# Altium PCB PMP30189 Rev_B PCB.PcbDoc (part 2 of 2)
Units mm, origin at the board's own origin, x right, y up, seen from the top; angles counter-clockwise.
Board outline 62.23 x 71.12 mm, 4 copper layers (Top Layer, Signal Layer 1, Signal Layer 2, Bottom Layer), stack 2.099 mm thick; 88 components, 42 nets, 247 pads, 90 vias.
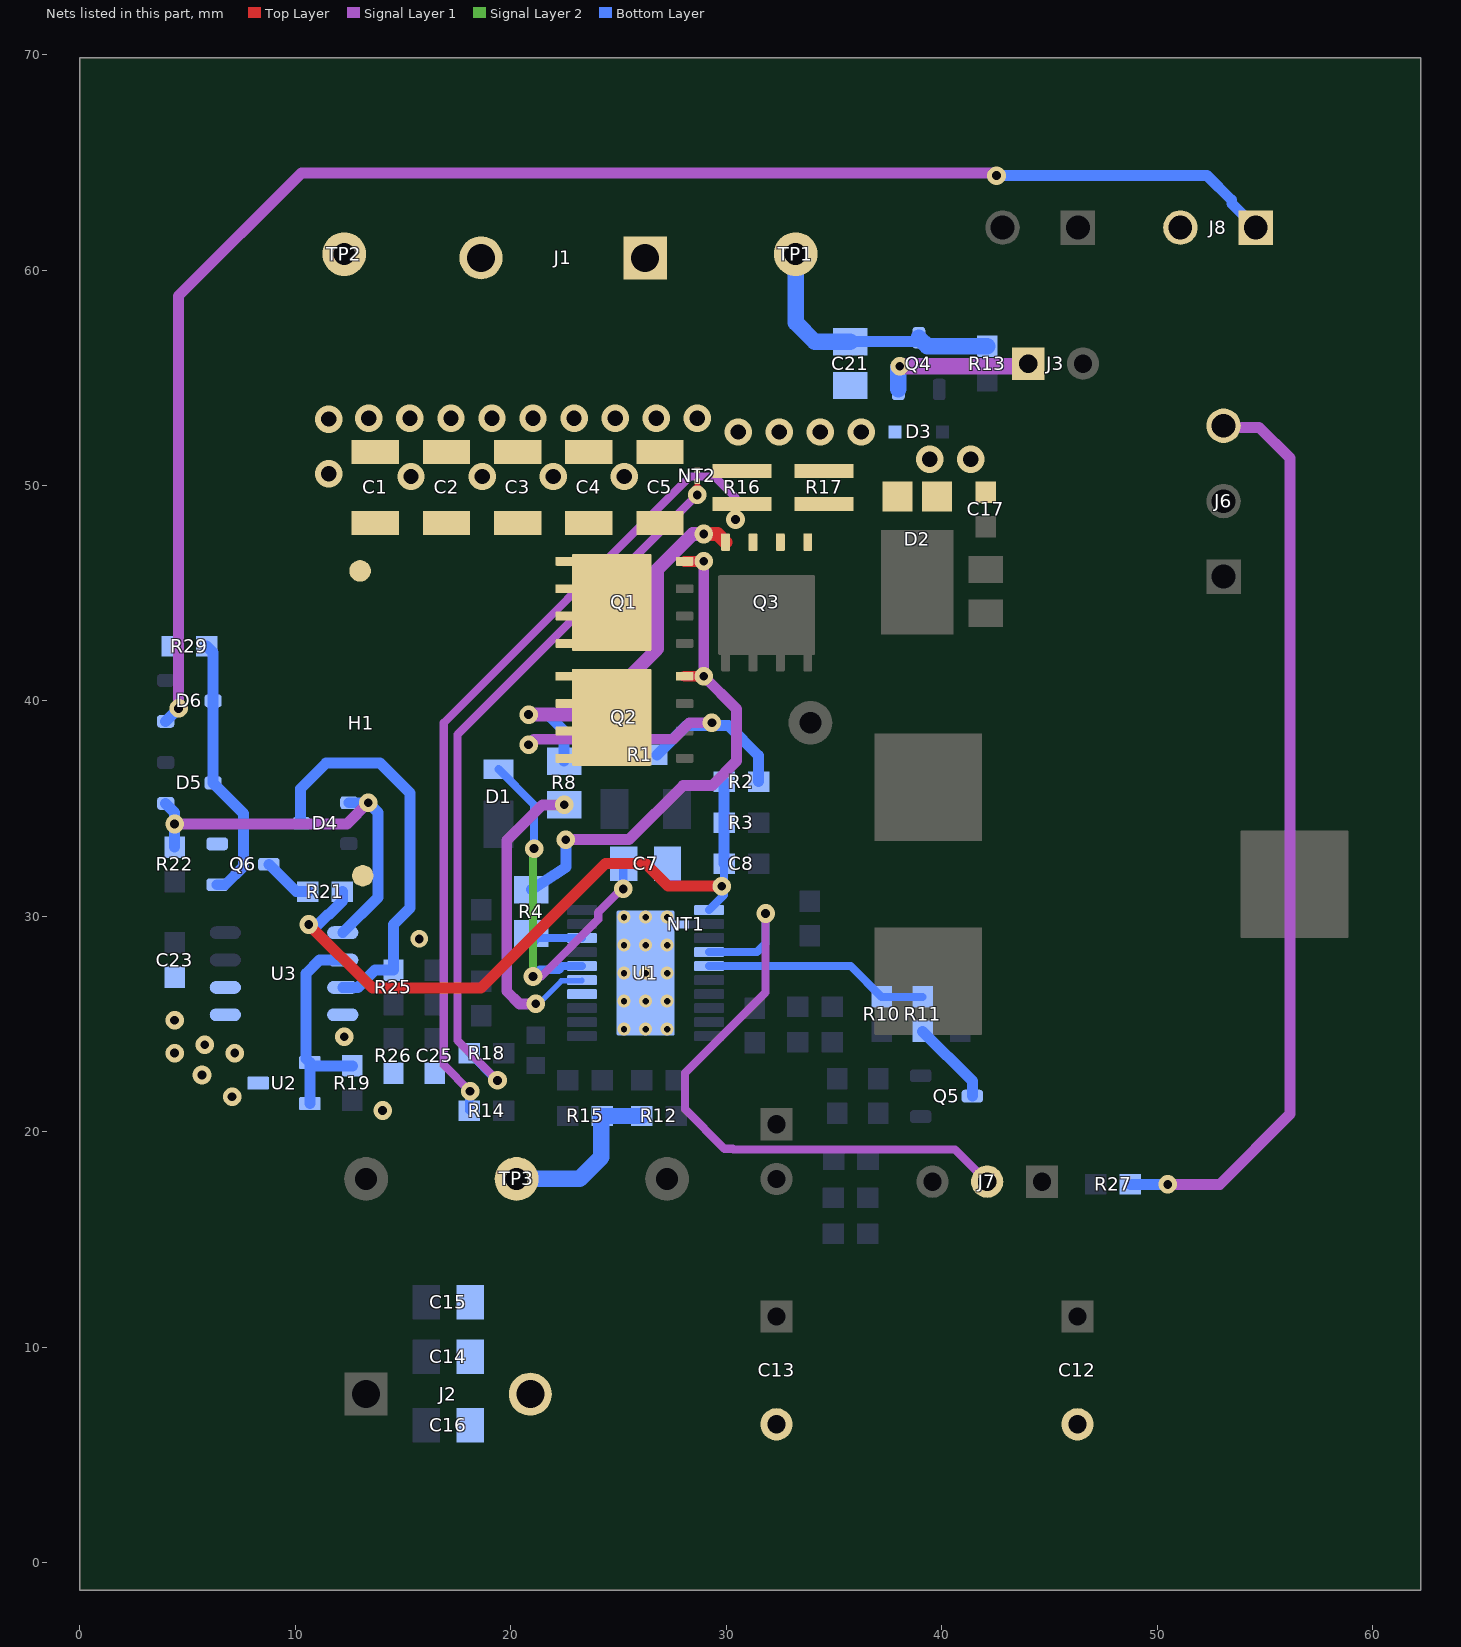
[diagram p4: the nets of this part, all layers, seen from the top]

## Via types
v1: diameter 0.864, hole 0.406, Top Layer to Bottom Layer, 51 vias
v2: diameter 1.27, hole 0.711, Top Layer to Bottom Layer, 21 vias
v3: diameter 0.6, hole 0.3, Top Layer to Bottom Layer, 9 vias
v4: diameter 0.6, hole 0.3, Top Layer to Bottom Layer, tented both sides, 6 vias
v5: diameter 0.813, hole 0.406, Top Layer to Bottom Layer, 2 vias
v6: diameter 0.864, hole 0.406, Top Layer to Bottom Layer, tented bottom, 1 vias

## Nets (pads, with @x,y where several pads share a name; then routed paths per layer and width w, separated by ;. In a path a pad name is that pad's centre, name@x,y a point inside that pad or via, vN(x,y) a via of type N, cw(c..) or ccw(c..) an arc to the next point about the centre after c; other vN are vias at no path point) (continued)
NetD4_1: D4.1 D5.1 R22.2 U3.1 | length 19.4
  Signal Layer 1 w0.508: v1(4.395,34.29) 12.395,34.29 v1(13.381,35.275)
  Bottom Layer w0.508: D5.1@3.98,35.245 4.395,34.83 v1(4.395,34.29) R22.2@4.395,33.22 ; U3.1@12.2,29.245 13.83,30.875 13.83,34.825 v1(13.381,35.275) D4.1@12.48,35.275
NetD4_3: D4.3 R25.2 U3.3 | length 19
  Bottom Layer w0.508: D4.3@10.28,34.325 10.237,34.368 10.237,35.925 11.431,37.119 13.92,37.119 15.317,35.722 15.317,30.388 14.555,29.626 R25.2@14.555,27.505 13.704,27.505 12.904,26.705 U3.3@12.2,26.705
NetD5_3: D5.3 D6.3 Q6.1 R29.2 | length 12.5
  Bottom Layer w0.508: R29.2@5.88,42.545 6.18,42.245 D6.3@6.18,40.005 D5.3@6.18,36.195 7.595,34.78 7.595,32.32 6.746,31.47 Q6.1@6.37,31.47
NetJ3_1: J3.1 Q4.2 | length 7.1
  Signal Layer 1 w0.762: v1(38.05,55.534) 43.892,55.534 J3.1@44.019,55.661
  Bottom Layer w0.762: Q4.2@37.989,54.461 37.989,55.473 v1(38.05,55.534)
NetJ6_3: J6.3 R27.1 | length 42.9
  Signal Layer 1 w0.508: v1(50.496,17.561) 52.909,17.561 56.171,20.823 56.171,51.271 54.737,52.705 53.157,52.705 J6.3@53.086,52.776
  Bottom Layer w0.508: R27.1@48.756,17.561 v1(50.496,17.561)
NetJ7_2: J7.2 U1.4 | length 30.2
  Signal Layer 1 w0.381: v1(31.827,30.134) 31.827,26.471 28.084,22.728 28.084,21.05 29.922,19.212 30.303,19.212 30.336,19.179 40.623,19.179 J7.2@42.114,17.688
  Bottom Layer w0.381: U1.4@29.205,28.345 31.435,28.345 31.827,28.737 v1(31.827,30.134)
NetNT2_1: NT2.1 R18.2 | length 34.8
  Top Layer w0.381: v1(28.652,49.565) v1@28.652,49.911
  Signal Layer 1 w0.381: v1@19.454,22.46 v1(19.381,22.387) 17.526,24.243 17.526,38.439 v1(28.652,49.565)
  Bottom Layer w0.381: R18.2@18.073,23.657 19.343,22.387 v1(19.381,22.387)
NetQ1_4: Q1.4 Q2.4 R4.2 | length 24.3
  Top Layer w0.508: Q2.4@28.068,41.148 v1(28.956,41.148) ; Q1.4@28.068,46.482 v1(28.956,46.482)
  Signal Layer 1 w0.508: v6(22.556,33.563) 25.486,33.563 27.991,36.068 29.337,36.068 30.48,37.211 30.48,39.624 v1(28.956,41.148) v1(28.956,46.482)
  Bottom Layer w0.508: R4.2@20.955,31.242 22.556,32.284 v6(22.556,33.563)
NetQ3_1: Q3.1 Q3.2 Q3.3 R14.2 R16.2 R17.2 | length 39.1
  Top Layer w0.381: v1(30.43,48.422) 30.43,48.917 R16.2@30.684,49.171
  Signal Layer 1 w0.381: v1(18.111,21.879) 16.891,23.1 16.891,38.989 28.321,50.419 29.464,50.419 30.43,49.453 v1(30.43,48.422)
  Bottom Layer w0.381: R14.2@18.073,20.99 18.073,21.841 v1(18.111,21.879)
NetQ3_4: Q3.4 R8.2 | length 18.3
  Top Layer w0.635: v1(28.956,47.752) 29.592,47.752 Q3.4@29.972,47.372
  Signal Layer 1 w0.635: v1(20.828,39.37) 23.749,39.37 26.797,42.418 26.797,46.101 28.448,47.752 v1(28.956,47.752)
  Bottom Layer w0.508: v1(20.828,39.37) 21.717,39.37 22.479,38.608 R8.2@22.479,37.211
NetQ5_3: Q5.3 R11.1 | length 4
  Bottom Layer w0.508: R11.1@39.116,24.665 41.425,22.356 Q5.3@41.425,21.655
NetQ6_3: Q6.3 R21.1 | length 2.3
  Bottom Layer w0.508: Q6.3@8.77,32.42 10.04,31.15 R21.1@10.58,31.15
NetR4_1: R4.1 U1.18 | length 2.4
  Bottom Layer w0.381: R4.1@21.032,28.776 21.251,28.995 U1.18@23.305,28.995
NetR8_1: R8.1 U1.15 | length 14.6
  Signal Layer 1 w0.508: v1(21.159,25.943) 20.397,25.943 19.812,26.529 19.812,33.528 21.463,35.179 v1(22.479,35.179)
  Bottom Layer w0.254: v1(21.159,25.943) 21.286,25.943 22.347,27.004 23.305,27.004 U1.15@23.305,27.045
NetR10_2: R10.2 R11.2 U1.5 | length 10.5
  Bottom Layer w0.381: U1.5@29.205,27.695 35.781,27.695 R10.2@37.211,26.265 R11.2@39.116,26.265
NetR12_1: R12.1 R15.2 TP3.1 | length 8.1
  Bottom Layer w0.762: TP3.1@20.27,17.815 23.191,17.815 24.207,18.831 24.207,20.698 R15.2@24.245,20.736 R12.1@26.074,20.736
NetR19_2: R19.2 U2.1 U2.2 U3.2 | length 10.1
  Bottom Layer w0.508: U2.2@10.675,21.31 U2.1@10.675,23.21 ; U3.2@12.2,27.975 11.126,27.975 10.491,27.34 10.491,23.394 U2.1@10.675,23.21 ; R19.2@12.65,23.06 10.826,23.06 U2.1@10.675,23.21
ON-OFF: D6.1 J8.1 | length 73.5
  Signal Layer 1 w0.508: v1(4.58,39.655) 4.58,58.809 10.287,64.516 42.418,64.516 v1(42.545,64.389)
  Bottom Layer w0.508: D6.1@3.98,39.055 v1(4.58,39.655) ; v1(42.545,64.389) 52.324,64.389 53.467,63.246 53.467,63.091 J8.1@54.582,61.976
OVV_24V: C8.1 R2.1 R3.2 R21.2 U1.1 | length 31.9
  Top Layer w0.508: v1(10.618,29.626) 13.573,26.672 18.619,26.672 24.397,32.45 26.255,32.45 27.301,31.404 v1(29.795,31.404)
  Bottom Layer w0.381: U1.1@29.205,30.295 29.9,30.99 C8.1@29.9,32.45
  Bottom Layer w0.508: v1(10.618,29.626) 11.043,29.626 11.507,30.09 11.557,30.09 12.18,30.713 R21.2@12.18,31.15 ; C8.1@29.9,32.45 R3.2@29.9,34.355 29.9,35.341 R2.1@29.9,36.26
SGND: C1.2 C2.2 C3.2 C4.2 C5.2 C7.2 C12.2 C13.2 C14.2 C15.2 C16.2 C17.2 C21.2 C23.2 C25.1 D2.1 D2.2 D3.2 J1.2 J2.2 J8.2 NT1.2 NT2.2 Q6.2 R16.1 R17.1 R26.1 R29.1 TP2.1 U1.14 U1.21@26.255,27.37 U2.3 U3.4 U3.5 U3.6
  other v1: 14.047,20.99 7.062,21.625 5.665,22.641 4.395,23.657 7.189,23.657 5.792,24.038 12.269,24.419 4.395,25.181
  other v2: 15.367,50.419 18.669,50.419 21.971,50.419 25.273,50.419 11.557,50.546 39.447,51.216 41.352,51.216 30.557,52.486 32.462,52.486 34.367,52.486 36.272,52.486 11.557,53.086 13.412,53.121 15.317,53.121 17.222,53.121 19.127,53.121 21.032,53.121 22.937,53.121 24.842,53.121 26.747,53.121 28.652,53.121
  other v3: 25.255,26.07 26.255,26.07 27.255,26.07 25.255,27.37 26.255,27.37 27.255,27.37 25.255,28.67 26.255,28.67 27.255,28.67
  other v4: 25.255,24.77 26.255,24.77 27.255,24.77 25.255,29.97 26.255,29.97 27.255,29.97
  other v5: 15.748,28.956
VCC-1: C7.1 D1.2 U1.16 | length 19.7
  Signal Layer 1 w0.381: v1@21.413,27.213 24.056,29.855 24.056,30.173 25.033,31.15 25.223,31.15 v1(25.223,31.277)
  Signal Layer 2 w0.381: v1(21.032,27.213) 21.032,33.097 v1(21.082,33.147)
  Bottom Layer w0.381: D1.2@19.431,36.835 21.082,35.184 v1(21.082,33.147) ; v1(21.032,27.213) 21.34,27.521 22.229,27.521 22.403,27.695 U1.16@23.305,27.695 ; v1(25.223,31.277) 25.223,32.434 C7.1@25.239,32.45
VIN: C1.1 C2.1 C3.1 C4.1 C5.1 C21.1 H1.1 H1.2 J1.1 Q1.5 Q1.6 Q1.7 Q1.8 Q1.9@24.683,44.577 Q2.5 Q2.6 Q2.7 Q2.8 Q2.9@24.683,39.243 Q4.3 R1.1 R2.2 R13.2 TP1.1 | length 28.7
  Signal Layer 1 w0.508: v1(20.828,37.973) 21.08,38.225 27.535,38.225 28.299,38.989 v1(29.337,38.989)
  Bottom Layer w0.508: R1.1@26.785,37.5 28.147,38.862 30.099,38.862 31.5,37.461 R2.2@31.5,36.26 ; C21.1@35.764,56.677 38.755,56.677 Q4.3@38.939,56.861
  Bottom Layer w0.762: TP1.1@33.224,60.741 33.224,57.566 34.114,56.677 C21.1@35.764,56.677 ; Q4.3@38.939,56.861 39.339,56.461 R13.2@42.114,56.461
pads on no net: D4.2 D5.2 D6.2 L1.3 Q1.9@23.873,43.127 Q1.9@23.873,44.577 Q1.9@23.873,46.027 Q1.9@25.653,43.127 Q1.9@25.653,44.577 Q1.9@25.653,46.027 Q2.9@23.873,37.793 Q2.9@23.873,39.243 Q2.9@23.873,40.693 Q2.9@25.653,37.793 Q2.9@25.653,39.243 Q2.9@25.653,40.693 Q3.9@30.427,43.177 Q3.9@30.427,44.957 Q3.9@31.877,43.177 Q3.9@31.877,44.957 Q3.9@33.327,43.177 Q3.9@33.327,44.957 U1.7 U1.10 U1.21@26.255,27.37 U3.7

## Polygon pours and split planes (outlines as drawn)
GND-1 on Bottom Layer "Bottom Layer-No Net" (solid, pour order 2): 37.034,36.357 36.399,36.992 27.255,36.992 26.493,36.23 26.493,35.976 26.493,32.039 28.36,30.173 28.455,30.173 28.455,24.32 28.398,24.263 28.398,23.82 28.236,23.657 24.969,23.657 23.318,23.657 22.937,23.276 22.937,21.662 22.937,20.011 26.657,16.291 28.88,14.069 39.003,14.069 40.209,15.275 40.251,21.793 40.251,23.105 40.209,23.146 40.209,26.705 37.796,29.118 37.796,29.626 37.796,35.595
SGND on Bottom Layer "S-GND Bottom" (solid, pour order 16): 1.279,67.31 59.514,67.31 59.513,0.797 59.64,0.67 1.267,0.67
24V on Bottom Layer "+24V Bottom" (solid, pour order 0): 9.602,14.005 17.095,14.005 17.095,3.845 9.602,3.845
GND-1 on Signal Layer 2 "Bottom Layer-No Net" (solid, pour order 4): 37.034,36.357 36.399,36.992 27.255,36.992 26.493,36.23 26.493,35.976 26.493,32.039 28.36,30.173 28.455,30.173 28.455,24.32 28.398,24.263 28.398,23.82 28.235,23.657 23.318,23.657 22.937,23.276 22.937,21.662 22.937,20.011 26.657,16.291 34.748,16.291 40.251,21.793 40.251,23.105 40.209,23.146 40.209,26.705 37.796,29.118 37.796,29.626 37.796,35.595
SGND on Signal Layer 2 "S-GND Mid-2" (solid, pour order 14): 1.281,67.31 59.514,67.31 59.513,0.797 59.64,0.67 1.269,0.67
SGND on Top Layer "TOP_LAYER_SGND_P020" (solid, remove dead copper, pour order 20): 24.638,23.876 28.194,23.876 29.718,25.4 29.718,29.972 29.21,30.48 23.368,30.48 21.849,28.961 21.849,25.764 23.045,24.568 23.94,24.568
NetC9_2 on Top Layer "Switch Node" (solid, pour order 6): 27.051,45.974 27.051,46.353 37.237,46.353 37.251,46.353 38.53,47.776 43.13,47.776 43.13,40.307 43.13,33.147 35.687,33.147 35.687,36.83 27.051,36.83
NetQ3_1 on Top Layer "Top Layer-No Net" (solid, pour order 8): 29.287,49.946 36.829,49.946 36.829,45.974 29.287,45.974
SGND on Top Layer "Signal Layer 1-No Net" (solid, pour order 10): 9.602,54.899 9.729,54.899 39.066,54.899 42.876,51.089 42.876,48.93 42.495,48.549 42.235,48.549 37.796,48.549 37.415,48.93 37.415,50.073 37.161,50.327 29.668,50.327 27.636,50.327 27.065,49.756 9.602,49.756
VIN on Top Layer "Vin" (solid, pour order 12): 1.397,67.091 59.64,67.091 59.64,56.55 58.497,55.407 9.348,55.407 8.713,54.772 8.713,49.132 26.797,49.132 26.797,33.613 22.126,28.942 1.397,28.942
24V on Top Layer "+24V" (solid, pour order 18): 1.27,19.735 33.292,19.735 34.42,20.863 34.42,25.615 36.703,27.898 36.703,31.369 38.646,31.369 49.911,31.369 57.75,23.53 59.514,21.767 59.513,22.888 59.513,0.73 59.466,0.683 2.618,0.683 1.27,2.03

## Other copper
Top Layer:
  rectangle net SGND: 28.144,50.327 31.192,51.089

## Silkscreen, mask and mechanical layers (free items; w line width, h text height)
Top Overlay:
  lines w0.254: 57.15,66.04 59.309,66.04
  text "-" at 17.78,68.961 h2.03 r180
  text "Vin" at 25.273,68.707 h2.03 r180
  text "+" at 27.051,68.453 h2.03 r270
  text "7V" at 46.863,67.691 h1.02 r180
  text "GND" at 51.562,67.564 h1.02 r180
  text "Fsw" at 42.799,67.437 h1.02 r180
  text "ON/OFF" at 59.055,67.437 h1.02 r180
  text "Vin-Trk" at 60.325,51.435 h1.02 r90
  text "GND" at 58.547,47.752 h1.02 r90
  text "Vout-Trk" at 60.452,41.148 h1.02 r90
  text "'.PRJ_Number'.PCB_Rev-" at 59.309,4.318 h2.75 r90
  text "+" at 10.16,1.905 h2.03 r270
  text "-" at 22.86,1.905 h2.03 r180
  text "Vout" at 13.97,0 h1.78
Top Solder:
  rectangle: 24.892,24.384 27.686,30.353
M1 Board Outline:
  the board outline again, w0.254
M2 Board Dimensions:
  rectangle: 0,-6.985 3.175,-3.81
  rectangle: 3.175,-10.16 12.7,-6.985
  lines w0.178: 0,-6.985 25.4,-6.985 ; 3.175,-10.16 3.175,-3.81 ; 6.35,-10.16 6.35,-3.81 ; 12.7,-10.16 12.7,-3.81 ; 19.05,-10.16 19.05,-3.81 ; 0,-10.16 25.4,-10.16 25.4,-3.81 0,-3.81 0,-10.16
M5 Assembly Top:
  lines w0.254: -7.417,-23.626 160.223,-23.626 ; -7.417,-18.462 160.274,-18.462 ; -7.417,-13.297 -7.417,-28.791 94.31,-28.791 160.274,-28.791 160.274,-13.297 -7.404,-13.297 -7.404,-28.791 32.614,-28.791 ; 55.194,-28.791 55.194,-13.297 ; 87.376,-18.462 87.376,-13.297 ; 108.712,-18.462 108.712,-13.297 ; 124.511,-28.956 124.511,-23.804
  text "COMPONENTS MARKED 'DNP' SHOULD NOT BE POPULATED." at 29.299,-8.09 h1.52
  text "ASSEMBLY VARIANT:" at 29.286,-11.024 h1.52
  text ".VariantName" at 55.601,-11.024 h1.52
  text "BOARD #:" at 57.099,-16.654 h1.52
  text ".PRJ_Number" at 70.955,-16.654 h1.52
  text "REV:" at 92.405,-16.654 h1.52
  text ".PCB_Rev" at 99.809,-16.654 h1.52
  text "SVN REV:" at 113.69,-16.654 h1.52
  text ".VersionControl_RevNumber" at 126.543,-16.654 h1.52
  text "TID #:" at 57.099,-21.819 h1.52
  text ".TID" at 70.955,-21.819 h1.52
  text "PLOT NAME =" at -5.804,-27.034 h1.52
  text ".plot_File_Name" at 14.656,-27.034 h1.52
  text "GENERATED    :" at 57.15,-27.034 h1.52
  text ".Print_Date" at 79.235,-27.034 h1.52
  text ".Print_Time" at 97.752,-27.034 h1.52
  text "TEXAS INSTRUMENTS" at 129.87,-27.034 h1.52
M6 Assembly Bottom:
  lines w0.254: -7.429,-18.474 160.261,-18.474 ; -7.379,-23.639 160.261,-23.639 ; 28.334,-28.969 28.334,-23.817 ; 44.133,-18.474 44.133,-13.31 ; 65.468,-18.474 65.468,-13.31 ; 97.65,-28.804 97.65,-13.31 ; 120.231,-28.804 160.249,-28.804 160.249,-13.31 -7.429,-13.31 -7.429,-28.804 58.534,-28.804 160.261,-28.804 160.261,-13.31
  text "COMPONENTS MARKED 'DNP' SHOULD NOT BE POPULATED." at 154.991,-8.077 h1.52
  text ".VariantName" at 128.473,-11.024 h1.52
  text "ASSEMBLY VARIANT:" at 154.864,-11.024 h1.52
  text ".PCB_Rev" at 53.035,-16.667 h1.52
  text "REV:" at 60.439,-16.667 h1.52
  text ".PRJ_Number" at 81.89,-16.667 h1.52
  text "BOARD #:" at 95.745,-16.667 h1.52
  text "PCB VIEWED FROM BOTTOM SIDE" at 158.648,-16.667 h1.52
  text ".TID" at 81.89,-21.831 h1.52
  text "TID #:" at 95.745,-21.831 h1.52
  text "TEXAS INSTRUMENTS" at 22.974,-27.047 h1.52
  text ".Print_Time" at 55.093,-27.047 h1.52
  text ".Print_Date" at 73.609,-27.047 h1.52
  text "GENERATED    :" at 95.694,-27.047 h1.52
  text ".plot_File_Name" at 138.189,-27.047 h1.52
  text "PLOT NAME =" at 158.648,-27.047 h1.52
M9 Title Sheet:
  drawing of 57 lines, arcs and shapes, not listed
  text "1" at 18.792,204.127 h1.78
  text "2" at 82.182,204.127 h1.78
  text "3" at 145.411,204.127 h1.78
  text "4" at 209.08,204.127 h1.78
  text "5" at 272.555,204.127 h1.78
  text "6" at 336.182,204.127 h1.78
  text "A" at -10.579,175.095 h1.78
  text "A" at 365.341,175.095 h1.78
  text "B" at -10.579,114.643 h1.78
  text "B" at 365.341,114.643 h1.78
  text "C" at -10.579,54.318 h1.78
  text "C" at 365.341,54.318 h1.78
  text "PROJECT TITLE:" at 288.125,7.048 h1.14
  text ".PRJ_Title" at 289.395,3.662 h1.78
  text "DESIGNED FOR:" at 288.125,-0.597 h1.14
  text ".PRJ_Customer" at 289.395,-4.153 h1.78
  text "D" at -10.579,-5.88 h1.78
  text "D" at 365.341,-5.88 h1.78
  text "FILE NAME:" at 288.125,-8.217 h1.14
  text ".PCB_File_Name_No_Path" at 289.395,-11.265 h1.78
  text "Texas Instruments (TI) and/or its licensors do not warrant the accuracy or completeness of this specification" at 161.9,-15.376 h1.14
  text "ENGINEER:" at 288.125,-15.583 h1.14
  text "LAYOUT BY:" at 326.352,-15.583 h1.14
  text "or any information contained therein. TI and/or its licensors do not warrant that this design will meet" at 160.757,-18.237 h1.14
  text ".PRJ_Engineer" at 289.395,-19.52 h1.78
  text ".PCB_Layout" at 327.635,-19.52 h1.78
  text "the specifications, will be suitable for your application or fit for any particular purpose, or will operate in" at 160.757,-21.099 h1.14
  text "ALTIUM DESIGNER VERSION:" at 326.352,-23.457 h1.14
  text "an implementation. TI and/or its licensors do not warrant that the design is production worthy. You should" at 160.757,-23.961 h1.14
  text "completely validate and test your design implementation to confirm the system functionality for your application." at 161.9,-26.822 h1.14
  text ".print_Scale" at 289.395,-26.843 h1.78
  text ".Application_BuildNumber" at 327.635,-26.843 h1.78
  text "1" at 18.792,-32.093 h1.78
  text "2" at 82.182,-32.093 h1.78
  text "3" at 145.411,-32.093 h1.78
  text "4" at 209.08,-32.093 h1.78
  text "5" at 272.555,-32.093 h1.78
  text "6" at 336.182,-32.093 h1.78
M10 Fab Notes:
  drawing of 173 lines, arcs and shapes, not listed
  text "DESIGN INFORMATION" at 314.402,157.505 h1.52
  text "MIN. TRACK WIDTH:" at 298.03,152.933 h1.52
  text "8" at 325.874,152.933 h1.52
  text "MIL" at 329.805,152.933 h1.52
  text "MIN. CLEARANCE:" at 298.03,149.581 h1.52
  text "0.2" at 324.35,149.581 h1.52
  text "mm" at 329.805,149.581 h1.52
  text "MIN. VIA PAD SIZE:" at 298.03,146.228 h1.52
  text "24" at 325.113,146.228 h1.52
  text "MIL" at 329.805,146.228 h1.52
  text "0.05mm (2MIL)" at 315.683,142.628 h1.52
  text "MINIMUM ANNULAR RING" at 289.667,142.52 h1.52
  text "EXTERNAL" at 333.666,142.52 h1.52
  text "PER" at 294.747,139.522 h1.52
  text "IPC-D-275 CLASS 2 LEVEL C" at 300.335,139.522 h1.52
  text "MIL, HOLES" at 338.136,136.67 h1.52
  text "+/-" at 328.168,136.652 h1.52
  text "+/-" at 349.86,136.652 h1.52
  text "REGISTRATION TOLERANCES:" at 289.667,136.525 h1.52
  text "METAL" at 320.142,136.525 h1.52
  text "5" at 334.777,136.525 h1.52
  text "3" at 355.935,136.525 h1.52
  text "MIL" at 358.888,136.525 h1.52
  text "+/-" at 349.86,133.655 h1.52
  text "HOLE SIZE TOLERANCE (UNLESS OTHERWISE SPECIFIED):" at 289.667,133.528 h1.52
  text "3" at 355.935,133.528 h1.52
  text "MIL" at 358.888,133.528 h1.52
  text "MATERIAL:" at 287.768,128.208 h1.52
  text "FR-4 High Tg" at 312.824,124.643 h1.52
  text "FR-408" at 298.462,124.425 h1.52
  text "OTHER" at 336.257,124.425 h1.52
  text "X" at 308.889,124.333 h1.52
  text "62 MIL (1.6mm) +/-10%" at 306.592,120.292 h1.52
  text "THICKNESS:" at 289.667,120.184 h1.52
  text "X" at 303.337,120.184 h1.52
  text "OTHER" at 339.229,120.184 h1.52
  text "TOLERANCE:" at 289.667,116.17 h1.52
  text "X" at 310.986,116.17 h1.52
  text "ANSI IPC-6012 TYPE 3 CLASS 2" at 315.734,116.17 h1.52
  text "OTHER +/-" at 315.734,112.208 h1.52
  text "BOW & TWIST:" at 289.667,108.22 h1.52
  text "X" at 310.986,108.22 h1.52
  text "ANSI IPC-6012 TYPE 3 CLASS 2" at 315.734,108.22 h1.52
  text "OTHER +/-" at 315.734,104.194 h1.52
  text "DRILLING:" at 287.768,100.676 h1.52
  text "REFERENCE:" at 289.667,97.705 h1.52
  text "X" at 306.132,97.705 h1.52
  text "AS SHOWN" at 310.882,97.705 h1.52
  text "X" at 329.018,97.705 h1.52
  text "NC_DRILL FILES" at 332.498,97.705 h1.52
  text "PTH COPPER THICKNESS:" at 289.667,93.691 h1.52
  text "X" at 318.375,93.691 h1.52
  text "20-30 um" at 321.855,93.691 h1.52
  text "OTHER" at 340.067,93.691 h1.52
  text "BOARD FINISH:" at 287.768,89.653 h1.52
  text "SILKSCREEN:" at 291.711,86.656 h1.52
  text "X" at 315.81,86.656 h1.52
  text "TOP" at 319.01,86.656 h1.52
  text "X" at 328.764,86.656 h1.52
  text "BOTTOM" at 331.99,86.656 h1.52
  text "SILKSCREEN COLOR:" at 291.711,82.414 h1.52
  text "X" at 315.783,82.414 h1.52
  text "WHITE" at 319.01,82.414 h1.52
  text "OTHER" at 331.99,82.414 h1.52
  text "X" at 319.111,78.37 h1.52
  text "GREEN" at 322.338,78.37 h1.52
  text "OTHER" at 338.035,78.37 h1.52
  text "SOLDER RESIST COLOR:" at 291.711,78.096 h1.52
  text "X" at 319.111,74.052 h1.52
  text "MATTE" at 322.338,74.052 h1.52
  text "SEMI-GLOSS" at 338.023,74.036 h1.52
  text "IMMERSION GOLD (ENIG)" at 314.718,69.264 h1.52
  text "ENEPIG" at 348.691,69.18 h1.52
  text "SURFACE FINISH:" at 287.768,69.155 h1.52
  text "X" at 309.969,69.155 h1.52
  text "IMM. TIN/SILVER OR EQUIV" at 296.139,65.167 h1.52
  text "OTHER" at 332.498,65.167 h1.52
  text "ARRAY/PANEL:" at 287.768,60.621 h1.52
  text "CUT AND TRIM PER M1 BOARD OUTLINE" at 314.718,60.512 h1.52
  text "N.C. ROUTE" at 314.718,56.658 h1.52
  text "X" at 331.964,56.658 h1.52
  text "V. SCORE" at 336.714,56.658 h1.52
  text "CERTIFICATION:" at 287.768,53.178 h1.52
  text "MATERIALS AND WORKMANSHIP FOR ALL PCBS" at 306.183,53.178 h1.52
  text "TO MEET OR EXCEED THE REQUIREMENTS OF:" at 306.183,50.689 h1.52
  text "X" at 296.696,47.222 h1.52
  text "ANSI IPC-A-600F CLASS ->" at 300.227,47.222 h1.52
  text "X" at 341.859,47.222 h1.52
  text "2" at 344.88,47.222 h1.52
  text "1" at 336.879,47.184 h1.52
  text "3" at 353.872,47.184 h1.52
  text "X" at 317.373,43.171 h1.52
  text "RoHS" at 320.852,43.171 h1.52
  text "OTHER" at 337.22,43.171 h1.52
  text "PER ORDER" at 347.305,43.171 h1.52
  text "ALL BOARDS MUST MEET OR EXCEED UL94-V0 REQUIREMENTS." at 288.468,38.964 h1.52
  text "PCB MUST BEAR THE UL94V-0 UL REGISTERED MATERIAL ID NUMBER" at 288.468,35.916 h1.52
  text "ADDITIONAL REQUIREMENTS:" at 287.768,31.512 h1.52
  text "MICROSECTION:" at 289.667,28.591 h1.52
  text "YES" at 312.673,28.591 h1.52
  text "REQUIRED" at 334.555,24.625 h1.52
  text "BARE BOARD ELEC. TEST:" at 289.667,24.553 h1.52
  text "NONE" at 322.833,24.553 h1.52
  text "X" at 331.329,24.553 h1.52
  text "PER ORDER" at 349.592,24.553 h1.52
M11 Gerber Information:
  lines w0.254: -7.417,-23.626 160.223,-23.626 ; -7.417,-18.462 160.274,-18.462 ; -7.417,-13.297 -7.417,-28.791 94.31,-28.791 160.274,-28.791 160.274,-13.297 -7.404,-13.297 -7.404,-28.791 32.614,-28.791 ; 55.194,-28.791 55.194,-13.297 ; 87.376,-18.462 87.376,-13.297 ; 108.712,-18.462 108.712,-13.297 ; 124.511,-28.956 124.511,-23.804
  text "BOARD #:" at 57.099,-16.654 h1.52
  text ".PRJ_Number" at 70.955,-16.654 h1.52
  text "REV:" at 92.405,-16.654 h1.52
  text ".PCB_Rev" at 99.809,-16.654 h1.52
  text "SVN REV:" at 113.69,-16.654 h1.52
  text ".VersionControl_RevNumber" at 126.543,-16.654 h1.52
  text "TID #:" at 57.099,-21.819 h1.52
  text ".TID" at 70.955,-21.819 h1.52
  text "PLOT NAME =" at -5.804,-27.034 h1.52
  text ".plot_File_Name" at 14.656,-27.034 h1.52
  text "GENERATED    :" at 57.15,-27.034 h1.52
  text ".Print_Date" at 79.235,-27.034 h1.52
  text ".Print_Time" at 97.752,-27.034 h1.52
  text "TEXAS INSTRUMENTS" at 129.87,-27.034 h1.52
M12 Stackup:
  drawing of 191 lines, arcs and shapes, not listed
  text "Layer" at 248.675,198.882 h1.52
  text "Name" at 259.086,198.882 h1.52
  text "Material" at 282.702,198.882 h1.52
  text "Thickness" at 304.54,198.882 h1.52
  text "Constant" at 321.046,198.882 h1.52
  text "Board Layer Stack" at 335.52,198.882 h1.52
  text "1" at 248.675,195.834 h1.52
  text "Top Overlay" at 259.086,195.834 h1.52
  text "2" at 248.675,192.786 h1.52
  text "Top Solder" at 259.086,192.786 h1.52
  text "Solder Resist" at 282.702,192.786 h1.52
  text "0.40mil" at 304.54,192.786 h1.52
  text "3.5" at 321.046,192.786 h1.52
  text "3" at 248.675,189.738 h1.52
  text "Top Layer" at 259.086,189.738 h1.52
  text "Copper" at 282.702,189.738 h1.52
  text "1.40mil" at 304.54,189.738 h1.52
  text "4" at 248.675,186.69 h1.52
  text "Dielectric1" at 259.086,186.69 h1.52
  text "FR-4" at 282.702,186.69 h1.52
  text "59.20mil" at 304.54,186.69 h1.52
  text "4.8" at 321.046,186.69 h1.52
  text "5" at 248.675,183.642 h1.52
  text "Bottom Layer" at 259.086,183.642 h1.52
  text "Copper" at 282.702,183.642 h1.52
  text "1.40mil" at 304.54,183.642 h1.52
  text "6" at 248.675,180.594 h1.52
  text "Bottom Solder" at 259.086,180.594 h1.52
  text "Solder Resist" at 282.702,180.594 h1.52
  text "0.40mil" at 304.54,180.594 h1.52
  text "3.5" at 321.046,180.594 h1.52
  text "7" at 248.675,177.546 h1.52
  text "Bottom Overlay" at 259.086,177.546 h1.52
Drill Drawing:
  circle w0.254: c136.241,79.797 r0.703
  lines w0.254: 135.538,64.693 136.943,64.693 136.241,63.288 135.538,64.693 ; 135.538,66.45 136.241,66.801 136.943,66.45 136.592,67.152 136.943,67.855 136.241,67.503 135.538,67.855 135.889,67.152 135.538,66.45 ; 135.538,69.611 136.943,69.611 136.943,71.016 135.538,71.016 135.538,69.611 ; 135.538,73.123 135.889,73.123 136.241,72.772 136.592,73.123 136.943,73.123 136.592,73.475 136.943,73.826 136.592,73.826 136.241,74.177 135.889,73.826 135.538,73.826 135.889,73.475 135.538,73.123 ; 135.538,75.933 135.538,76.285 135.889,76.636 135.538,76.987 135.538,77.338 135.889,77.338 136.241,76.987 136.592,77.338 136.943,77.338 136.943,76.987 136.592,76.636 136.943,76.285 136.943,75.933 136.592,75.933 136.241,76.285 135.889,75.933 135.538,75.933 ; 135.538,82.256 136.943,82.256 136.943,83.661 135.538,83.661 135.538,82.256 ; 135.819,82.537 136.662,82.537 136.662,83.38 135.819,83.38 135.819,82.537
  lines w0.305: 134.264,62.34 216.377,62.34 ; 134.264,84.469 216.377,84.469 ; 142.854,59.179 142.854,87.63 ; 151.29,59.179 151.29,87.63 ; 167.469,59.179 167.469,87.63 ; 174.057,59.179 174.057,87.63 ; 183.593,59.179 183.593,87.63 ; 201.978,59.179 201.978,87.63 ; 134.264,59.179 216.377,59.179 216.377,87.63 134.264,87.63 134.264,59.179
  text "Symbol" at 136.161,85.417 h1.83
  text "Quantity" at 143.802,85.417 h1.83
  text "Finished Hole Size" at 152.238,85.417 h1.83
  text "Plated" at 168.418,85.417 h1.83
  text "Hole Type" at 175.005,85.417 h1.83
  text "Drill Layer Pair" at 184.541,85.417 h1.83
  text "Hole Tolerance" at 202.927,85.417 h1.83
  text "15" at 143.802,82.256 h1.52
  text "11.81mil (0.300mm)" at 152.238,82.256 h1.52
  text "PTH" at 168.418,82.256 h1.52
  text "Round" at 175.005,82.256 h1.52
  text "Top Layer - Bottom Layer" at 184.541,82.256 h1.52
  text "54" at 143.802,79.095 h1.52
  text "16.00mil (0.406mm)" at 152.238,79.095 h1.52
  text "PTH" at 168.418,79.095 h1.52
  text "Round" at 175.005,79.095 h1.52
  text "Top Layer - Bottom Layer" at 184.541,79.095 h1.52
  text "21" at 143.802,75.933 h1.52
  text "28.00mil (0.711mm)" at 152.238,75.933 h1.52
  text "PTH" at 168.418,75.933 h1.52
  text "Round" at 175.005,75.933 h1.52
  text "Top Layer - Bottom Layer" at 184.541,75.933 h1.52
  text "11" at 143.802,72.772 h1.52
  text "33.46mil (0.850mm)" at 152.238,72.772 h1.52
  text "PTH" at 168.418,72.772 h1.52
  text "Round" at 175.005,72.772 h1.52
  text "Top Layer - Bottom Layer" at 184.541,72.772 h1.52
  text "6" at 143.802,69.611 h1.52
  text "40.00mil (1.016mm)" at 152.238,69.611 h1.52
  text "PTH" at 168.418,69.611 h1.52
  text "Round" at 175.005,69.611 h1.52
  text "Top Layer - Bottom Layer" at 184.541,69.611 h1.52
  text "7" at 143.802,66.45 h1.52
  text "43.31mil (1.100mm)" at 152.238,66.45 h1.52
  text "PTH" at 168.418,66.45 h1.52
  text "Round" at 175.005,66.45 h1.52
  text "Top Layer - Bottom Layer" at 184.541,66.45 h1.52
  text "4" at 143.802,63.288 h1.52
  text "51.18mil (1.300mm)" at 152.238,63.288 h1.52
  text "PTH" at 168.418,63.288 h1.52
  text "Round" at 175.005,63.288 h1.52
  text "Top Layer - Bottom Layer" at 184.541,63.288 h1.52
  text "118 Total" at 143.802,60.127 h1.52
M17 Embedded Cavity:
  text ".Layer_Name" at 14.656,-21.806 h1.52
M18 Embedded Assembly:
  text ".Layer_Name" at 14.656,-21.806 h1.52
M19 Embedded Keepout:
  text ".Layer_Name" at 14.656,-21.806 h1.52

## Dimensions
0,-10.16 to 25.4,-10.16 on M2 Board Dimensions
0,69.85 to 62.23,-1.27 on M2 Board Dimensions
0,0 to 62.23,-1.27 on M2 Board Dimensions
